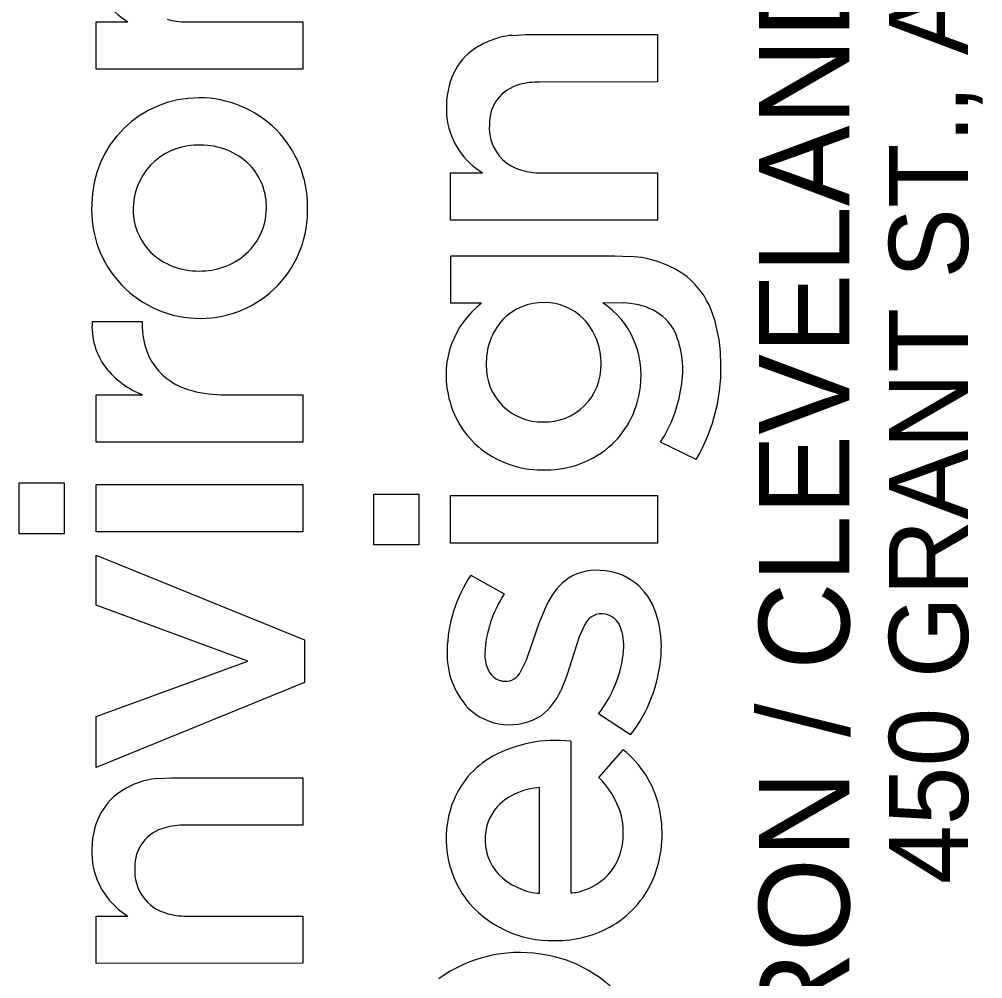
# Model space of a CAD drawing. Extents: x -0.4 to 34, y 0 to 22.
# Drawn here: x 32.377 to 32.984, y 3.278 to 3.882 of the extents above; entities that cross this region are included whole.
import ezdxf

# ---------------------------------------------------------------- set-up
doc = ezdxf.new("R2010")
doc.units = 0
doc.layers.add('SH_Data', color=7, linetype='Continuous')

msp = doc.modelspace()

# ---------------------------------------------------------------- linework, layer by layer
at = {"layer": 'SH_Data'}
for p, q in [((32.42542, 3.88066), (32.44552, 3.88071)), ((32.42542, 3.85086), (32.42542, 3.88066)), ((32.48222, 3.88071), (32.55569, 3.88071)), ((32.55569, 3.88071), (32.55571, 3.85096)), ((32.68784, 3.8722), (32.69634, 3.87266)), ((32.69634, 3.87266), (32.77916, 3.87266)), ((32.77916, 3.87266), (32.77917, 3.84287)), ((32.55571, 3.85096), (32.42542, 3.85086)), ((32.77917, 3.84287), (32.70485, 3.8428)), ((32.64888, 3.7855), (32.66897, 3.78555)), ((32.64888, 3.75569), (32.64888, 3.7855)), ((32.70568, 3.78555), (32.77915, 3.78555)), ((32.77915, 3.78555), (32.77917, 3.75579)), ((32.77917, 3.75579), (32.64888, 3.75569)), ((32.6489, 3.70336), (32.64889, 3.73322)), ((32.64889, 3.73322), (32.75236, 3.73322)), ((32.75236, 3.73322), (32.76191, 3.73285)), ((32.66836, 3.70336), (32.6489, 3.70336)), ((32.75763, 3.70356), (32.74487, 3.70361)), ((32.42299, 3.69193), (32.45454, 3.69193)), ((32.42542, 3.64577), (32.45473, 3.64579)), ((32.42542, 3.61593), (32.42542, 3.64577)), ((32.50413, 3.64581), (32.55571, 3.64573)), ((32.55571, 3.64573), (32.55565, 3.61593)), ((32.55565, 3.61593), (32.42542, 3.61593)), ((32.8036, 3.60491), (32.7812, 3.61598)), ((32.37705, 3.55818), (32.37705, 3.59026)), ((32.37705, 3.59026), (32.40543, 3.59026)), ((32.40543, 3.59026), (32.40543, 3.55818)), ((32.42542, 3.55942), (32.42542, 3.58928)), ((32.42542, 3.58928), (32.55571, 3.58928)), ((32.55571, 3.58928), (32.55571, 3.55942)), ((32.60051, 3.55111), (32.60051, 3.58319)), ((32.60051, 3.58319), (32.62889, 3.58319)), ((32.62889, 3.58319), (32.62889, 3.55111)), ((32.64888, 3.55234), (32.64888, 3.5822)), ((32.64888, 3.5822), (32.77917, 3.5822)), ((32.77917, 3.5822), (32.77917, 3.55234)), ((32.40543, 3.55818), (32.37705, 3.55818)), ((32.55571, 3.55942), (32.42542, 3.55942)), ((32.77917, 3.55234), (32.64888, 3.55234)), ((32.62889, 3.55111), (32.60051, 3.55111)), ((32.42542, 3.51327), (32.42542, 3.5446)), ((32.42542, 3.5446), (32.5567, 3.4913)), ((32.66151, 3.53207), (32.68268, 3.52025)), ((32.70483, 3.50258), (32.71036, 3.51526)), ((32.52117, 3.47798), (32.42542, 3.51327)), ((32.69675, 3.47868), (32.70483, 3.50258)), ((32.73342, 3.50101), (32.72985, 3.4933)), ((32.5567, 3.4913), (32.5567, 3.46441)), ((32.72985, 3.4933), (32.72213, 3.46882)), ((32.42542, 3.44294), (32.52117, 3.47798)), ((32.69299, 3.47117), (32.69675, 3.47868)), ((32.72213, 3.46882), (32.71822, 3.45921)), ((32.5567, 3.46441), (32.42542, 3.41086)), ((32.42542, 3.41086), (32.42542, 3.44294)), ((32.76214, 3.43141), (32.74198, 3.44469)), ((32.72453, 3.42747), (32.72463, 3.33195)), ((32.74228, 3.40465), (32.75768, 3.422)), ((32.46439, 3.40397), (32.47289, 3.40443)), ((32.47289, 3.40443), (32.55571, 3.40443)), ((32.55571, 3.40443), (32.55571, 3.37465)), ((32.70489, 3.33182), (32.70489, 3.39834)), ((32.55571, 3.37465), (32.4814, 3.37457)), ((32.70361, 3.33165), (32.70489, 3.33182)), ((32.42542, 3.31728), (32.44552, 3.31733)), ((32.42542, 3.28747), (32.42542, 3.31728)), ((32.48222, 3.31733), (32.55569, 3.31733)), ((32.55569, 3.31733), (32.55571, 3.28756)), ((32.55571, 3.28756), (32.42542, 3.28747))]:
    msp.add_line(p, q, dxfattribs=at)
for points in [[(32.42542, 3.85086), (32.42542, 3.88066), (32.44552, 3.88071)], [(32.48222, 3.88071), (32.55569, 3.88071), (32.55571, 3.85096), (32.42542, 3.85086)], [(32.68784, 3.8722), (32.69634, 3.87266), (32.77916, 3.87266), (32.77917, 3.84287), (32.70485, 3.8428)], [(32.64888, 3.75569), (32.64888, 3.7855), (32.66897, 3.78555)], [(32.70568, 3.78555), (32.77915, 3.78555), (32.77917, 3.75579), (32.64888, 3.75569)], [(32.66836, 3.70336), (32.6489, 3.70336), (32.64889, 3.73322), (32.75236, 3.73322), (32.76191, 3.73285)], [(32.75763, 3.70356), (32.74487, 3.70361)], [(32.42299, 3.69193), (32.45454, 3.69193)], [(32.50413, 3.64581), (32.55571, 3.64573), (32.55565, 3.61593), (32.42542, 3.61593)], [(32.42542, 3.61593), (32.42542, 3.64577), (32.45473, 3.64579)], [(32.8036, 3.60491), (32.7812, 3.61598)], [(32.66151, 3.53207), (32.68268, 3.52025)], [(32.69299, 3.47117), (32.69675, 3.47868), (32.70483, 3.50258), (32.71036, 3.51526)], [(32.73342, 3.50101), (32.72985, 3.4933), (32.72213, 3.46882), (32.71822, 3.45921)], [(32.76214, 3.43141), (32.74198, 3.44469)], [(32.72453, 3.42747), (32.72463, 3.33195)], [(32.74228, 3.40465), (32.75768, 3.422)], [(32.46439, 3.40397), (32.47289, 3.40443), (32.55571, 3.40443), (32.55571, 3.37465), (32.4814, 3.37457)], [(32.70361, 3.33165), (32.70489, 3.33182), (32.70489, 3.39834)], [(32.42542, 3.28747), (32.42542, 3.31728), (32.44552, 3.31733)], [(32.48222, 3.31733), (32.55569, 3.31733), (32.55571, 3.28756), (32.42542, 3.28747)]]:
    msp.add_lwpolyline(points, dxfattribs=at)
for points in [[(32.37705, 3.55818), (32.37705, 3.59026), (32.40543, 3.59026), (32.40543, 3.55818)], [(32.42542, 3.55942), (32.42542, 3.58928), (32.55571, 3.58928), (32.55571, 3.55942)], [(32.60051, 3.55111), (32.60051, 3.58319), (32.62889, 3.58319), (32.62889, 3.55111)], [(32.64888, 3.55234), (32.64888, 3.5822), (32.77917, 3.5822), (32.77917, 3.55234)], [(32.42542, 3.41086), (32.42542, 3.44294), (32.52117, 3.47798), (32.42542, 3.51327), (32.42542, 3.5446), (32.5567, 3.4913), (32.5567, 3.46441)]]:
    msp.add_lwpolyline(points, close=True, dxfattribs=at)
for centre, radius, start, end in [((32.47027, 3.92141), 0.04763, 188.96462, 238.69865), ((32.47027, 3.92141), 0.04763, 188.96462, 238.69865), ((32.48183, 3.92286), 0.04215, 254.08913, 270.52838), ((32.48183, 3.92286), 0.04215, 254.08913, 270.52838), ((32.69216, 3.82251), 0.04988, 94.97056, 130.22484), ((32.69216, 3.82251), 0.04988, 94.97056, 130.22484), ((32.68694, 3.83085), 0.04016, 132.22383, 161.68229), ((32.68694, 3.83085), 0.04016, 132.22383, 161.68229), ((32.70217, 3.82642), 0.05602, 162.27398, 187.79173), ((32.70217, 3.82642), 0.05602, 162.27398, 187.79173), ((32.69828, 3.81689), 0.02498, 103.68683, 182.21395), ((32.69828, 3.81689), 0.02498, 103.68683, 182.21395), ((32.70453, 3.79679), 0.04601, 89.60515, 105.33026), ((32.70453, 3.79679), 0.04601, 89.60515, 105.33026), ((32.49014, 3.76543), 0.0674, 89.84756, 179.64047), ((32.49014, 3.76543), 0.0674, 89.84756, 179.64047), ((32.49057, 3.76474), 0.0681, 359.54009, 90.21138), ((32.49057, 3.76474), 0.0681, 359.54009, 90.21138), ((32.69372, 3.82624), 0.04763, 188.96462, 238.69865), ((32.69372, 3.82624), 0.04763, 188.96462, 238.69865), ((32.7008, 3.81381), 0.02757, 175.58441, 255.13816), ((32.7008, 3.81381), 0.02757, 175.58441, 255.13816), ((32.48923, 3.76263), 0.0404, 87.04809, 175.57259), ((32.48923, 3.76263), 0.0404, 87.04809, 175.57259), ((32.49204, 3.75999), 0.04299, 45.84264, 90.98008), ((32.49204, 3.75999), 0.04299, 45.84264, 90.98008), ((32.49458, 3.76421), 0.03821, 357.88569, 44.15902), ((32.49458, 3.76421), 0.03821, 357.88569, 44.15902), ((32.70529, 3.82769), 0.04215, 254.08913, 270.52838), ((32.70529, 3.82769), 0.04215, 254.08913, 270.52838), ((32.49083, 3.76209), 0.06819, 176.8344, 270.40384), ((32.49083, 3.76209), 0.06819, 176.8344, 270.40384), ((32.48729, 3.7625), 0.03848, 175.15378, 221.14706), ((32.48729, 3.7625), 0.03848, 175.15378, 221.14706), ((32.49123, 3.76139), 0.06749, 270.06243, 2.37759), ((32.49123, 3.76139), 0.06749, 270.06243, 2.37759), ((32.49446, 3.76318), 0.0383, 308.28936, 359.43468), ((32.49446, 3.76318), 0.0383, 308.28936, 359.43468), ((32.48919, 3.76607), 0.04228, 223.09994, 268.80895), ((32.48919, 3.76607), 0.04228, 223.09994, 268.80895), ((32.49096, 3.7679), 0.04418, 266.56515, 308.06078), ((32.49096, 3.7679), 0.04418, 266.56515, 308.06078), ((32.75907, 3.66789), 0.06503, 53.40344, 87.49062), ((32.75907, 3.66789), 0.06503, 53.40344, 87.49062), ((32.76517, 3.68039), 0.05141, 21.60748, 50.5577), ((32.76517, 3.68039), 0.05141, 21.60748, 50.5577), ((32.70292, 3.65813), 0.05692, 127.37482, 192.22468), ((32.70292, 3.65813), 0.05692, 127.37482, 192.22468), ((32.70693, 3.66927), 0.0346, 88.47302, 136.42562), ((32.70693, 3.66927), 0.0346, 88.47302, 136.42562), ((32.70814, 3.66963), 0.03424, 44.27195, 90.47623), ((32.70814, 3.66963), 0.03424, 44.27195, 90.47623), ((32.71421, 3.65829), 0.05472, 352.1125, 55.92295), ((32.71421, 3.65829), 0.05472, 352.1125, 55.92295), ((32.75666, 3.65725), 0.04633, 65.01687, 88.8011), ((32.75666, 3.65725), 0.04633, 65.01687, 88.8011), ((32.7626, 3.67155), 0.03085, 26.26808, 63.80301), ((32.7626, 3.67155), 0.03085, 26.26808, 63.80301), ((32.73069, 3.66714), 0.08835, 1.15143, 21.3627), ((32.73069, 3.66714), 0.08835, 1.15143, 21.3627), ((32.46616, 3.68882), 0.04329, 175.87313, 216.34747), ((32.46616, 3.68882), 0.04329, 175.87313, 216.34747), ((32.50087, 3.68948), 0.04639, 176.9688, 209.60636), ((32.50087, 3.68948), 0.04639, 176.9688, 209.60636), ((32.71141, 3.66602), 0.0401, 137.46739, 182.33237), ((32.71141, 3.66602), 0.0401, 137.46739, 182.33237), ((32.70368, 3.666), 0.03996, 358.57141, 43.53765), ((32.70368, 3.666), 0.03996, 358.57141, 43.53765), ((32.73565, 3.66154), 0.05953, 349.30734, 23.43071), ((32.73565, 3.66154), 0.05953, 349.30734, 23.43071), ((32.70538, 3.66244), 0.11383, 329.6388, 3.25998), ((32.70538, 3.66244), 0.11383, 329.6388, 3.25998), ((32.47466, 3.69716), 0.05511, 218.09809, 248.7907), ((32.47466, 3.69716), 0.05511, 218.09809, 248.7907), ((32.49514, 3.68814), 0.04079, 211.94466, 253.2028), ((32.49514, 3.68814), 0.04079, 211.94466, 253.2028), ((32.70645, 3.6637), 0.03511, 178.88208, 271.08374), ((32.70645, 3.6637), 0.03511, 178.88208, 271.08374), ((32.70818, 3.66404), 0.03546, 268.27882, 1.55016), ((32.70818, 3.66404), 0.03546, 268.27882, 1.55016), ((32.50465, 3.7165), 0.07069, 252.46555, 269.57296), ((32.50465, 3.7165), 0.07069, 252.46555, 269.57296), ((32.70988, 3.65708), 0.05887, 313.74196, 353.8554), ((32.70988, 3.65708), 0.05887, 313.74196, 353.8554), ((32.70738, 3.66334), 0.08771, 327.31495, 351.57478), ((32.70738, 3.66334), 0.08771, 327.31495, 351.57478), ((32.70463, 3.65696), 0.05837, 190.75182, 231.28919), ((32.70463, 3.65696), 0.05837, 190.75182, 231.28919), ((32.70954, 3.65901), 0.06051, 269.6361, 312.70877), ((32.70954, 3.65901), 0.06051, 269.6361, 312.70877), ((32.70632, 3.66112), 0.06269, 232.46061, 272.59022), ((32.70632, 3.66112), 0.06269, 232.46061, 272.59022), ((32.7406, 3.5026), 0.03263, 80.17192, 122.51969), ((32.7406, 3.5026), 0.03263, 80.17192, 122.51969), ((32.74278, 3.49824), 0.03667, 47.79344, 84.68918), ((32.74278, 3.49824), 0.03667, 47.79344, 84.68918), ((32.73636, 3.48258), 0.08973, 146.53104, 178.7571), ((32.73636, 3.48258), 0.08973, 146.53104, 178.7571), ((32.74661, 3.49713), 0.04053, 125.51182, 153.41595), ((32.74661, 3.49713), 0.04053, 125.51182, 153.41595), ((32.73788, 3.4946), 0.04267, 14.9966, 46.20632), ((32.73788, 3.4946), 0.04267, 14.9966, 46.20632), ((32.74519, 3.4789), 0.07495, 146.51121, 176.91007), ((32.74519, 3.4789), 0.07495, 146.51121, 176.91007), ((32.74384, 3.49631), 0.01143, 76.66094, 155.7053), ((32.74384, 3.49631), 0.01143, 76.66094, 155.7053), ((32.74397, 3.49511), 0.01256, 21.5098, 78.52618), ((32.74397, 3.49511), 0.01256, 21.5098, 78.52618), ((32.71044, 3.48674), 0.07121, 355.83062, 15.39138), ((32.71044, 3.48674), 0.07121, 355.83062, 15.39138), ((32.72592, 3.48766), 0.03209, 354.57264, 22.06805), ((32.72592, 3.48766), 0.03209, 354.57264, 22.06805), ((32.69666, 3.48238), 0.05005, 177.53659, 222.79318), ((32.69666, 3.48238), 0.05005, 177.53659, 222.79318), ((32.6931, 3.48233), 0.02276, 178.47474, 211.08679), ((32.6931, 3.48233), 0.02276, 178.47474, 211.08679), ((32.68248, 3.49149), 0.0757, 321.81101, 354.79685), ((32.68248, 3.49149), 0.0757, 321.81101, 354.79685), ((32.68952, 3.4882), 0.09219, 321.9777, 355.87384), ((32.68952, 3.4882), 0.09219, 321.9777, 355.87384), ((32.68331, 3.4767), 0.01148, 212.23676, 268.37769), ((32.68331, 3.4767), 0.01148, 212.23676, 268.37769), ((32.68342, 3.47589), 0.01067, 267.71603, 333.73375), ((32.68342, 3.47589), 0.01067, 267.71603, 333.73375), ((32.68098, 3.4758), 0.04077, 308.08772, 335.98736), ((32.68098, 3.4758), 0.04077, 308.08772, 335.98736), ((32.68599, 3.47535), 0.0375, 225.98539, 302.47965), ((32.68599, 3.47535), 0.0375, 225.98539, 302.47965), ((32.7152, 3.34414), 0.08384, 83.61499, 118.28755), ((32.7152, 3.34414), 0.08384, 83.61499, 118.28755), ((32.71744, 3.37167), 0.06443, 13.53365, 51.36148), ((32.71744, 3.37167), 0.06443, 13.53365, 51.36148), ((32.70239, 3.36906), 0.05583, 118.83082, 160.62438), ((32.70239, 3.36906), 0.05583, 118.83082, 160.62438), ((32.46871, 3.35428), 0.04988, 94.96958, 130.22249), ((32.46871, 3.35428), 0.04988, 94.96958, 130.22249), ((32.70378, 3.36556), 0.05486, 19.03571, 45.44059), ((32.70378, 3.36556), 0.05486, 19.03571, 45.44059), ((32.70785, 3.35609), 0.04235, 94.00805, 130.88169), ((32.70785, 3.35609), 0.04235, 94.00805, 130.88169), ((32.46348, 3.36263), 0.04015, 132.22192, 161.68183), ((32.46348, 3.36263), 0.04015, 132.22192, 161.68183), ((32.70048, 3.36628), 0.02985, 132.98507, 177.179), ((32.70048, 3.36628), 0.02985, 132.98507, 177.179), ((32.71041, 3.36612), 0.06437, 160.52012, 215.78311), ((32.71041, 3.36612), 0.06437, 160.52012, 215.78311), ((32.71069, 3.3697), 0.047, 344.60586, 17.007), ((32.71069, 3.3697), 0.047, 344.60586, 17.007), ((32.70635, 3.36921), 0.07579, 339.3542, 13.37853), ((32.70635, 3.36921), 0.07579, 339.3542, 13.37853), ((32.47872, 3.35819), 0.05601, 162.27355, 187.79185), ((32.47872, 3.35819), 0.05601, 162.27355, 187.79185), ((32.47482, 3.34867), 0.02498, 103.68646, 182.21874), ((32.47482, 3.34867), 0.02498, 103.68646, 182.21874), ((32.48108, 3.32856), 0.04601, 89.60494, 105.3284), ((32.48108, 3.32856), 0.04601, 89.60494, 105.3284), ((32.7017, 3.36503), 0.03115, 175.00126, 223.28301), ((32.7017, 3.36503), 0.03115, 175.00126, 223.28301), ((32.7224, 3.36715), 0.03504, 288.00773, 343.55078), ((32.7224, 3.36715), 0.03504, 288.00773, 343.55078), ((32.47026, 3.35802), 0.04762, 188.96199, 238.70369), ((32.47026, 3.35802), 0.04762, 188.96199, 238.70369), ((32.47735, 3.34558), 0.02756, 175.58538, 255.14386), ((32.47735, 3.34558), 0.02756, 175.58538, 255.14386), ((32.70891, 3.37363), 0.04231, 225.06188, 262.79738), ((32.70891, 3.37363), 0.04231, 225.06188, 262.79738), ((32.71894, 3.3652), 0.0626, 300.94269, 338.73225), ((32.71894, 3.3652), 0.0626, 300.94269, 338.73225), ((32.72474, 3.35216), 0.02021, 269.7003, 294.8711), ((32.72474, 3.35216), 0.02021, 269.7003, 294.8711), ((32.71253, 3.37054), 0.06872, 217.74516, 271.65431), ((32.71253, 3.37054), 0.06872, 217.74516, 271.65431), ((32.48183, 3.35948), 0.04215, 254.09162, 270.52835), ((32.48183, 3.35948), 0.04215, 254.09162, 270.52835), ((32.71549, 3.37241), 0.07056, 269.20477, 300.33412), ((32.71549, 3.37241), 0.07056, 269.20477, 300.33412), ((32.69229, 3.20792), 0.08641, 81.19402, 125.99844), ((32.69229, 3.20792), 0.08641, 81.19402, 125.99844), ((32.69458, 3.21132), 0.08272, 37.85208, 82.40204), ((32.69458, 3.21132), 0.08272, 37.85208, 82.40204)]:
    msp.add_arc(centre, radius, start, end, dxfattribs=at)

# ---------------------------------------------------------------- texts
for s, height, p in [('450 GRANT ST., AKRON, OH  44311', 0.0498462, (32.97489, 3.33738)), ('AKRON / CLEVELAND / COLUMBUS', 0.056969, (32.90012, 3.138))]:
    msp.add_text(s, height=height, rotation=90, dxfattribs=at).set_placement(p)

doc.saveas('drawing.dxf')
